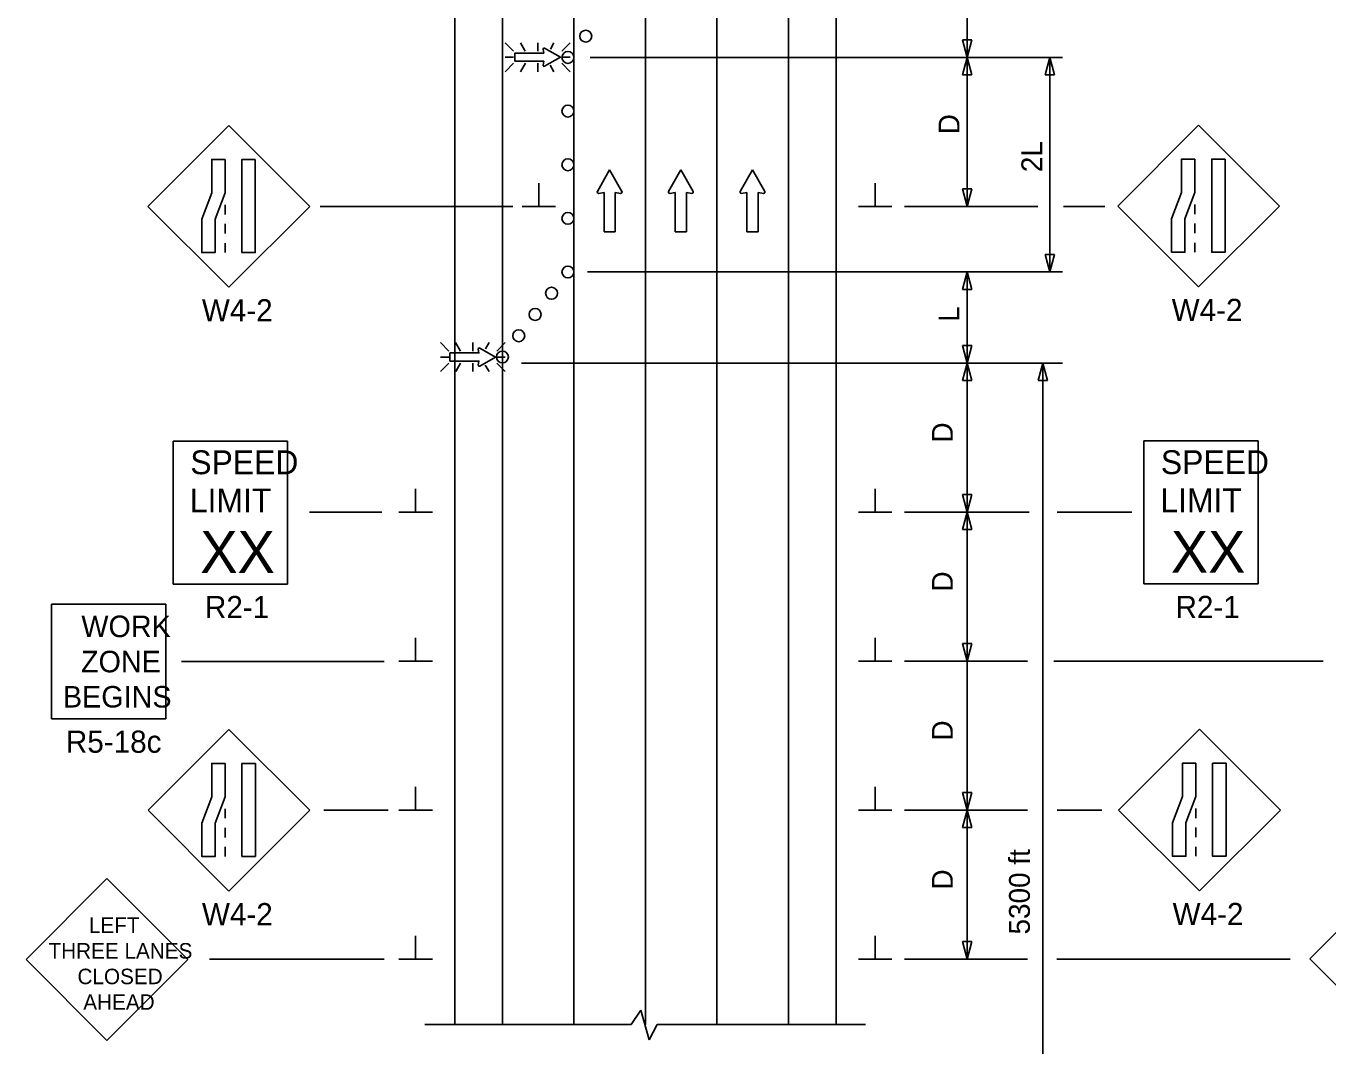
# Model space of a CAD drawing. Extents: x 16724 to 18475, y 7025 to 8210.
# Drawn here: x 16724.4 to 17161.5, y 7539.2 to 7881.5 of the extents above; entities that cross this region are included whole.
import ezdxf

# ---------------------------------------------------------------- set-up
doc = ezdxf.new("R2010")
doc.units = 0
for name, color, linetype in [('MT_SCRATCH_LEVEL_E', 7, 'Continuous'), ('PAVT_EDGE_EX', 7, 'Continuous'), ('TRAFFIC_SIGNS_PR', 7, 'Continuous'), ('TYPICAL_TEXT_DIMEN_PR', 7, 'Continuous')]:
    doc.layers.add(name, color=color, linetype=linetype)

msp = doc.modelspace()

# ---------------------------------------------------------------- linework, layer by layer
at = {"layer": 'MT_SCRATCH_LEVEL_E'}
for p, q in [((16920.29, 7833.22), (16916.18, 7825.98)), ((16924.44, 7825.98), (16920.29, 7833.22)), ((16944.2, 7833.22), (16940.09, 7825.98)), ((16948.34, 7825.98), (16944.2, 7833.22)), ((16968.25, 7833.22), (16964.14, 7825.98)), ((16972.4, 7825.98), (16968.25, 7833.22)), ((16916.66, 7825.3), (16918.44, 7825.61)), ((16918.44, 7825.61), (16918.44, 7812.36)), ((16922.18, 7812.36), (16922.18, 7825.61)), ((16922.18, 7825.61), (16923.96, 7825.3)), ((16940.57, 7825.3), (16942.35, 7825.61)), ((16942.35, 7825.61), (16942.35, 7812.36)), ((16946.09, 7812.36), (16946.09, 7825.61)), ((16946.09, 7825.61), (16947.87, 7825.3)), ((16964.62, 7825.3), (16966.4, 7825.61)), ((16966.4, 7825.61), (16966.4, 7812.36)), ((16970.14, 7812.36), (16970.14, 7825.61)), ((16970.14, 7825.61), (16971.92, 7825.3)), ((16918.44, 7812.36), (16922.18, 7812.36)), ((16942.35, 7812.36), (16946.09, 7812.36)), ((16966.4, 7812.36), (16970.14, 7812.36))]:
    msp.add_line(p, q, dxfattribs=at)
for centre, start, end in [((16916.59, 7825.76), 150.4248, 279.9638), ((16924.03, 7825.76), 260.0362, 29.7731), ((16940.49, 7825.76), 150.4248, 279.9638), ((16947.93, 7825.76), 260.0362, 29.7731), ((16964.55, 7825.76), 150.4248, 279.9638), ((16971.99, 7825.76), 260.0362, 29.7731)]:
    msp.add_arc(centre, 0.463, start, end, dxfattribs=at)
at = {"layer": 'PAVT_EDGE_EX'}
for p, q in [((16868.3, 8210.42), (16868.3, 7546.41)), ((16884.3, 8210.42), (16884.3, 7546.41)), ((16980.3, 8210.42), (16980.3, 7546.41)), ((16996.3, 8210.42), (16996.3, 7546.41)), ((16908.3, 7546.41), (16908.3, 8134.51)), ((16932.3, 7546.41), (16932.3, 8134.51)), ((16956.3, 7546.41), (16956.3, 8134.51))]:
    msp.add_line(p, q, dxfattribs=at)
for points in [[(16908.3, 7846.41), (16908.3, 7871.41)], [(16932.3, 7846.41), (16932.3, 7871.41)], [(16956.3, 7846.41), (16956.3, 7871.41)], [(16932.3, 7746.41), (16932.3, 7771.41)], [(16956.3, 7746.41), (16956.3, 7771.41)], [(16908.3, 7646.41), (16908.3, 7671.41)], [(16932.3, 7646.41), (16932.3, 7671.41)], [(16956.3, 7646.41), (16956.3, 7671.41)], [(16908.3, 7546.41), (16908.3, 7571.41)], [(16932.3, 7546.41), (16932.3, 7571.41)], [(16956.3, 7546.41), (16956.3, 7571.41)]]:
    msp.add_lwpolyline(points, dxfattribs=at)
at = {"layer": 'TRAFFIC_SIGNS_PR'}
for p, q in [((16888.07, 7873.02), (16885.25, 7875.84)), ((16890.37, 7875.84), (16891.99, 7873.02)), ((16896.15, 7873.02), (16896.15, 7875.84)), ((16901.62, 7875.84), (16900.42, 7873.75)), ((16907.06, 7875.84), (16904.24, 7873.02)), ((16888.07, 7870.99), (16885.25, 7870.99)), ((16888.07, 7868.96), (16885.25, 7866.13)), ((16892.02, 7868.96), (16890.39, 7866.14)), ((16896.15, 7868.96), (16896.15, 7866.14)), ((16900.34, 7868.32), (16901.6, 7866.14)), ((16904.24, 7870.99), (16907.06, 7870.99)), ((16907.06, 7866.14), (16904.24, 7868.96)), ((16792.46, 7848.09), (16765.3, 7820.94)), ((16819.61, 7820.94), (16792.46, 7848.09)), ((17118.03, 7848.21), (17090.88, 7821.06)), ((17145.18, 7821.06), (17118.03, 7848.21)), ((16765.3, 7820.94), (16792.46, 7793.79)), ((16791.21, 7821.43), (16791.21, 7818.23)), ((16792.46, 7793.79), (16819.61, 7820.94)), ((17090.88, 7821.06), (17118.03, 7793.91)), ((17116.78, 7821.55), (17116.78, 7818.35)), ((17118.03, 7793.91), (17145.18, 7821.06)), ((16791.21, 7815.03), (16791.21, 7811.83)), ((17116.78, 7815.15), (17116.78, 7811.95)), ((16791.21, 7808.63), (16791.21, 7805.43)), ((17116.78, 7808.75), (17116.78, 7805.55)), ((16866.29, 7772.4), (16863.47, 7775.22)), ((16868.59, 7775.22), (16870.22, 7772.4)), ((16874.38, 7772.4), (16874.38, 7775.22)), ((16879.85, 7775.22), (16878.64, 7773.12)), ((16885.28, 7775.21), (16882.46, 7772.4)), ((16866.29, 7770.36), (16863.47, 7770.36)), ((16866.29, 7768.33), (16863.47, 7765.51)), ((16870.24, 7768.33), (16868.62, 7765.51)), ((16874.38, 7768.33), (16874.38, 7765.51)), ((16878.56, 7767.7), (16879.82, 7765.51)), ((16882.46, 7770.36), (16885.28, 7770.36)), ((16885.28, 7765.51), (16882.46, 7768.33)), ((16773.77, 7742.2), (16812.17, 7742.2)), ((16773.77, 7694.2), (16773.77, 7742.2)), ((16812.17, 7694.2), (16812.17, 7742.2)), ((17099.6, 7742.24), (17138, 7742.24)), ((17099.6, 7694.24), (17099.6, 7742.24)), ((17138, 7694.24), (17138, 7742.24)), ((16773.77, 7694.2), (16812.17, 7694.2)), ((17099.6, 7694.24), (17138, 7694.24)), ((16732.96, 7649.02), (16732.96, 7687.42)), ((16732.96, 7687.42), (16771.36, 7687.42)), ((16771.36, 7649.02), (16771.36, 7687.42)), ((16732.96, 7649.02), (16771.36, 7649.02)), ((16792.48, 7645.44), (16765.33, 7618.29)), ((16819.64, 7618.29), (16792.48, 7645.44)), ((17118.34, 7645.51), (17091.19, 7618.36)), ((17145.5, 7618.36), (17118.34, 7645.51)), ((16765.33, 7618.29), (16792.48, 7591.14)), ((16791.24, 7618.78), (16791.24, 7615.58)), ((16792.48, 7591.14), (16819.64, 7618.29)), ((17091.19, 7618.36), (17118.34, 7591.2)), ((17117.1, 7618.85), (17117.1, 7615.65)), ((17118.34, 7591.2), (17145.5, 7618.36)), ((16791.24, 7612.38), (16791.24, 7609.18)), ((17117.1, 7612.45), (17117.1, 7609.25)), ((16791.24, 7605.98), (16791.24, 7602.78)), ((17117.1, 7606.05), (17117.1, 7602.85)), ((16751.54, 7595.34), (16724.38, 7568.19)), ((16778.69, 7568.19), (16751.54, 7595.34)), ((17182.47, 7595.55), (17155.32, 7568.39)), ((16724.38, 7568.19), (16751.54, 7541.04)), ((16751.54, 7541.04), (16778.69, 7568.19)), ((17155.32, 7568.39), (17182.47, 7541.24))]:
    msp.add_line(p, q, dxfattribs=at)
for points in [[(16897.98, 7873.67), (16898.21, 7872.37), (16888.49, 7872.37), (16888.49, 7869.63), (16898.21, 7869.63), (16897.98, 7868.33)], [(16898.48, 7867.97), (16903.79, 7870.99), (16898.48, 7874.03)], [(16876.21, 7773.05), (16876.43, 7771.75), (16866.71, 7771.75), (16866.71, 7769.01), (16876.43, 7769.01), (16876.2, 7767.7)], [(16876.71, 7767.35), (16882.01, 7770.36), (16876.7, 7773.4)]]:
    msp.add_lwpolyline(points, dxfattribs=at)
for points in [[(17116.78, 7836.8), (17116.78, 7825.61), (17113.44, 7816.73), (17113.44, 7805.55), (17108.95, 7805.55), (17108.95, 7816.73), (17112.29, 7825.61), (17112.29, 7836.8)], [(17126.92, 7836.8), (17126.92, 7805.55), (17122.43, 7805.55), (17122.43, 7836.8)], [(16791.21, 7836.68), (16791.21, 7825.49), (16787.86, 7816.61), (16787.86, 7805.43), (16783.37, 7805.43), (16783.37, 7816.61), (16786.71, 7825.49), (16786.71, 7836.68)], [(16801.34, 7836.68), (16801.34, 7805.43), (16796.85, 7805.43), (16796.85, 7836.68)], [(16791.24, 7634.03), (16791.24, 7622.84), (16787.89, 7613.96), (16787.89, 7602.78), (16783.4, 7602.78), (16783.4, 7613.96), (16786.74, 7622.84), (16786.74, 7634.03)], [(16801.37, 7634.03), (16801.37, 7602.78), (16796.88, 7602.78), (16796.88, 7634.03)], [(17117.1, 7634.09), (17117.1, 7622.91), (17113.75, 7614.03), (17113.75, 7602.85), (17109.26, 7602.85), (17109.26, 7614.03), (17112.6, 7622.91), (17112.6, 7634.09)], [(17127.23, 7634.09), (17127.23, 7602.85), (17122.74, 7602.85), (17122.74, 7634.09)]]:
    msp.add_lwpolyline(points, close=True, dxfattribs=at)
for centre in [(16912.29, 7878.06), (16906.29, 7870.92), (16906.29, 7852.92), (16906.29, 7834.92), (16906.29, 7816.92), (16906.29, 7798.92), (16900.8, 7791.78), (16895.3, 7784.66), (16889.8, 7777.53), (16884.3, 7770.4)]:
    msp.add_circle(centre, 2, dxfattribs=at)
for centre, start, end in [((16898.32, 7873.73), 61.4833, 189.9593), ((16898.32, 7868.27), 170.7308, 298.8916), ((16876.54, 7773.1), 61.4833, 189.9593), ((16876.54, 7767.65), 170.7308, 298.8916)]:
    msp.add_arc(centre, 0.341, start, end, dxfattribs=at)
at = {"layer": 'TYPICAL_TEXT_DIMEN_PR'}
for p, q in [((17040.3, 7870.92), (17040.3, 7899.48)), ((17040.3, 7870.92), (17038.72, 7876.78)), ((17038.72, 7876.78), (17040.3, 7876.78)), ((17040.3, 7876.78), (17041.87, 7876.78)), ((17041.87, 7876.78), (17040.3, 7870.92)), ((16913.79, 7870.92), (17072.34, 7870.92)), ((17038.72, 7865.06), (17040.3, 7870.92)), ((17040.3, 7870.92), (17040.3, 7820.92)), ((17040.3, 7870.92), (17041.87, 7865.06)), ((17066.53, 7865.06), (17068.1, 7870.92)), ((17068.1, 7870.92), (17069.67, 7865.06)), ((17068.1, 7870.92), (17068.1, 7798.92)), ((17040.3, 7865.06), (17038.72, 7865.06)), ((17041.87, 7865.06), (17040.3, 7865.06)), ((17068.1, 7865.06), (17066.53, 7865.06)), ((17069.67, 7865.06), (17068.1, 7865.06)), ((16896.55, 7820.92), (16896.55, 7828.7)), ((17009.42, 7820.92), (17009.42, 7828.7)), ((17040.3, 7820.92), (17038.72, 7826.78)), ((17038.72, 7826.78), (17040.3, 7826.78)), ((17040.3, 7826.78), (17041.87, 7826.78)), ((17041.87, 7826.78), (17040.3, 7820.92)), ((17068.1, 7825.79), (17068.1, 7822.02)), ((16823.18, 7820.92), (16887.86, 7820.92)), ((16902.18, 7820.92), (16890.93, 7820.92)), ((17015.05, 7820.92), (17003.8, 7820.92)), ((17064.08, 7820.92), (17019.3, 7820.92)), ((17086.52, 7820.92), (17072.64, 7820.92)), ((17068.1, 7798.92), (17066.53, 7804.78)), ((17066.53, 7804.78), (17068.1, 7804.78)), ((17068.1, 7804.78), (17069.67, 7804.78)), ((17069.67, 7804.78), (17068.1, 7798.92)), ((16912.9, 7798.92), (17072.34, 7798.92)), ((17038.72, 7793.06), (17040.3, 7798.92)), ((17040.3, 7768.35), (17040.3, 7798.92)), ((17040.3, 7798.92), (17041.87, 7793.06)), ((17040.3, 7793.06), (17038.72, 7793.06)), ((17041.87, 7793.06), (17040.3, 7793.06)), ((17040.3, 7768.35), (17038.72, 7774.22)), ((17038.72, 7774.22), (17040.3, 7774.22)), ((17040.3, 7774.22), (17041.87, 7774.22)), ((17041.87, 7774.22), (17040.3, 7768.35)), ((16890.68, 7768.35), (17072.34, 7768.35)), ((17038.72, 7762.49), (17040.3, 7768.35)), ((17040.3, 7768.35), (17041.87, 7762.49)), ((17040.3, 7768.35), (17040.3, 7718.35)), ((17064.16, 7762.49), (17065.73, 7768.35)), ((17065.73, 7768.35), (17067.3, 7762.49)), ((17065.73, 7768.35), (17065.73, 7489.56)), ((17040.3, 7762.49), (17038.72, 7762.49)), ((17041.87, 7762.49), (17040.3, 7762.49)), ((17065.73, 7762.49), (17064.16, 7762.49)), ((17067.3, 7762.49), (17065.73, 7762.49)), ((16855.17, 7718.35), (16855.17, 7726.14)), ((17009.42, 7718.35), (17009.42, 7726.14)), ((17040.3, 7718.35), (17038.72, 7724.22)), ((17038.72, 7724.22), (17040.3, 7724.22)), ((17040.3, 7724.22), (17041.87, 7724.22)), ((17041.87, 7724.22), (17040.3, 7718.35)), ((16843.78, 7718.35), (16819.59, 7718.35)), ((16849.55, 7718.35), (16860.8, 7718.35)), ((17015.05, 7718.35), (17003.8, 7718.35)), ((17061.12, 7718.35), (17019.3, 7718.35)), ((17038.72, 7712.49), (17040.3, 7718.35)), ((17040.3, 7718.35), (17040.3, 7668.35)), ((17040.3, 7718.35), (17041.87, 7712.49)), ((17095.58, 7718.35), (17070.5, 7718.35)), ((17040.3, 7712.49), (17038.72, 7712.49)), ((17041.87, 7712.49), (17040.3, 7712.49)), ((16855.17, 7668.35), (16855.17, 7676.14)), ((17009.42, 7668.35), (17009.42, 7676.14)), ((17040.3, 7668.35), (17038.72, 7674.22)), ((17038.72, 7674.22), (17040.3, 7674.22)), ((17040.3, 7674.22), (17041.87, 7674.22)), ((17041.87, 7674.22), (17040.3, 7668.35)), ((16844.65, 7668.19), (16776.6, 7668.19)), ((16849.55, 7668.35), (16860.8, 7668.35)), ((17015.05, 7668.35), (17003.8, 7668.35)), ((17060.63, 7668.35), (17019.3, 7668.35)), ((17040.3, 7668.35), (17040.3, 7618.35)), ((17159.89, 7668.35), (17069.46, 7668.35)), ((16855.17, 7618.35), (16855.17, 7626.14)), ((17009.42, 7618.35), (17009.42, 7626.14)), ((17040.3, 7618.35), (17038.72, 7624.22)), ((17038.72, 7624.22), (17040.3, 7624.22)), ((17040.3, 7624.22), (17041.87, 7624.22)), ((17041.87, 7624.22), (17040.3, 7618.35)), ((16824.35, 7618.35), (16846.01, 7618.35)), ((16849.55, 7618.35), (16860.8, 7618.35)), ((17015.05, 7618.35), (17003.8, 7618.35)), ((17060.63, 7618.35), (17019.3, 7618.35)), ((17038.72, 7612.49), (17040.3, 7618.35)), ((17040.3, 7618.35), (17040.3, 7568.35)), ((17040.3, 7618.35), (17041.87, 7612.49)), ((17085.5, 7618.35), (17070.5, 7618.35)), ((17040.3, 7612.49), (17038.72, 7612.49)), ((17041.87, 7612.49), (17040.3, 7612.49)), ((16855.17, 7568.35), (16855.17, 7576.14)), ((17009.42, 7568.35), (17009.42, 7576.14)), ((17040.3, 7568.35), (17038.72, 7574.22)), ((17038.72, 7574.22), (17040.3, 7574.22)), ((17040.3, 7574.22), (17041.87, 7574.22)), ((17041.87, 7574.22), (17040.3, 7568.35)), ((16844.65, 7568.33), (16785.93, 7568.33)), ((16849.55, 7568.35), (16860.8, 7568.35)), ((17015.05, 7568.35), (17003.8, 7568.35)), ((17060.63, 7568.35), (17019.3, 7568.35)), ((17148.82, 7568.35), (17070.44, 7568.35)), ((16930.81, 7551.21), (16927.55, 7546.41)), ((16933.55, 7541.27), (16930.81, 7551.21)), ((16927.55, 7546.41), (16858.21, 7546.41)), ((16936.29, 7546.41), (16933.55, 7541.27)), ((17006.21, 7546.41), (16936.29, 7546.41))]:
    msp.add_line(p, q, dxfattribs=at)

# ---------------------------------------------------------------- texts
at = {"layer": 'TRAFFIC_SIGNS_PR'}
for s, height, p in [('W4-2', 7.44, (16783.41, 7782.35)), ('W4-2', 7.44, (17108.99, 7782.47)), ('SPEED', 8, (16779.54, 7731.06)), ('SPEED', 8, (17105.37, 7731.1)), ('LIMIT', 8, (16779.38, 7718.26)), ('LIMIT', 8, (17105.21, 7718.3)), ('XX', 14.031, (16782.88, 7697.96)), ('XX', 14.031, (17108.71, 7698)), ('R2-1', 7.44, (16784.45, 7682.76)), ('R2-1', 7.44, (17110.28, 7682.8)), ('WORK', 7.217, (16742.96, 7676.39)), ('ZONE', 7.217, (16742.84, 7664.58)), ('BEGINS', 7.217, (16736.77, 7652.77)), ('R5-18c', 7.44, (16737.77, 7637.58)), ('W4-2', 7.44, (16783.44, 7579.7)), ('W4-2', 7.44, (17109.3, 7579.76)), ('LEFT', 5.2, (16745.48, 7577.12)), ('THREE LANES', 5.2, (16731.93, 7568.52)), ('CLOSED', 5.2, (16741.66, 7559.92)), ('AHEAD', 5.2, (16743.6, 7551.32))]:
    msp.add_text(s, height=height, dxfattribs=at).set_placement(p)
at = {"layer": 'TYPICAL_TEXT_DIMEN_PR'}
for s, p in [('D', (17037.74, 7845.14)), ('2L', (17065.54, 7832.42)), ('L', (17037.74, 7782.21)), ('D', (17035.5, 7741.68)), ('D', (17035.5, 7691.68)), ('D', (17035.5, 7641.68)), ('5300 ft', (17061.38, 7576.6)), ('D', (17035.5, 7591.68))]:
    msp.add_text(s, height=7, rotation=90, dxfattribs=at).set_placement(p)

doc.saveas('drawing.dxf')
